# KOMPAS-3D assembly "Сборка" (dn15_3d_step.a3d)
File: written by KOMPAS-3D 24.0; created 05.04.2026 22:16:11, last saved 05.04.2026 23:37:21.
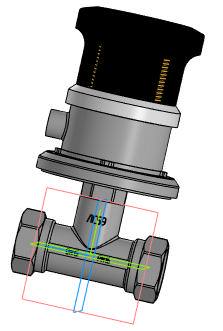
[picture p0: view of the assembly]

Document properties: Автор: tyuri; Полное имя файла: D:\Аутсорс\Клапан балансировочный автоматический DN.ru VBA0000E-T Ду15 Ру16\DN15\Исходные файлы\dn15_3d_step.a3d

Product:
- Component [detail]: Деталь  | qty 1  | Автор: tyuri; additional columns: Типовые; source file: Деталь_2 - Деталь.m3d
- Component [detail]: Деталь  | designation Деталь_1  | qty 1  | Автор: tyuri; additional columns: Типовые; source file: Деталь_1 - Деталь.m3d
- Component [detail]: Деталь  | qty 1  | Масса: 0.342386; Автор: tyuri; additional columns: Типовые; source file: Деталь_3 - Деталь.m3d
- Body: Тело 2  | qty 1
    Масса: 0.711103
- Part/product: Сборка
    Масса: 1.053489

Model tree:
1. Смещенная плоскость:1
     Расстояние = 12
2. Эскиз:2  (labels: Грань.Твердое тело1)
3. Элемент вращения:2
     Угол 1 = 360
4. Эскиз:4
5. Элемент выдавливания:3  (labels: Грань.Твердое тело1)
     Расстояние 1 = -2.00544
6. Эскиз:5  (with: Грань.Элемент выдавливания:3)
7. Элемент вращения:3
     Угол 1 = 360
8. Эскиз:6  (with: Грань.Элемент выдавливания:3)
9. Элемент выдавливания:4  (with: Грань.Элемент выдавливания:3)
     Расстояние 1 = 0.001; Расстояние 2 = 42.5244
10. Элемент вращения:5  (with: Грань.Элемент вращения:1, Грань.Элемент выдавливания:1)  (labels: Грань.Твердое тело1; Твердое тело1)
     Угол 1 = 360

Referenced files in D:\Аутсорс\Клапан балансировочный автоматический DN.ru VBA0000E-T Ду15 Ру16\DN15\Исходные файлы\: Деталь_1 - Деталь.m3d, Деталь_2 - Деталь.m3d, Деталь_3 - Деталь.m3d
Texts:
  DN15        PN16
  ЛС59
  Деталь_1 Деталь
  Ось Y.Начало координат
  Ось Z.Начало координат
